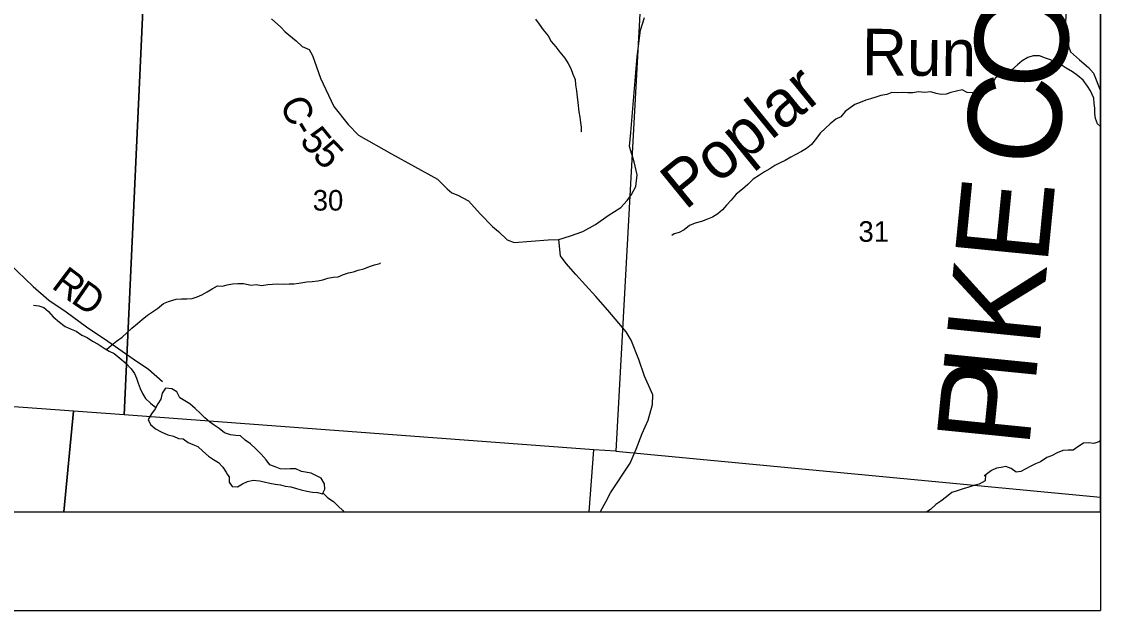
# Model space of a CAD drawing. Extents: x 5.6 to 39.6, y 0.7 to 22.7.
# Drawn here: x 12.858 to 15.052, y 14.707 to 15.903 of the extents above; entities that cross this region are included whole.
import ezdxf

# ---------------------------------------------------------------- set-up
doc = ezdxf.new("R2010")
doc.units = 0
doc.layers.add('Default', color=7, linetype='Continuous')
doc.layers.add('SH_Data', color=7, linetype='Continuous')

msp = doc.modelspace()

# ---------------------------------------------------------------- linework, layer by layer
at = {"layer": 'Default'}
for p, q in [((15.0518, 14.9373), (15.0518, 15.9625)), ((11.8881, 14.9074), (12.9445, 14.9074)), ((12.9445, 14.9074), (14.0121, 14.9074))]:
    msp.add_line(p, q, dxfattribs=at)
for points in [[(8.2518, 18.5322), (8.2518, 14.9074), (15.0518, 14.9074), (15.0518, 18.0251)], [(8.2518, 18.5322), (8.2518, 14.9074), (15.0518, 14.9074), (15.0518, 18.0251)], [(8.2518, 18.5322), (8.2518, 14.9074), (15.0518, 14.9074), (15.0518, 18.0251)], [(14.6817, 16.1552), (14.682, 16.155), (14.6933, 16.1477), (14.796, 16.0871), (14.8885, 16.041), (14.9244, 16.0245), (14.9584, 16.0122), (14.9777, 16.0079), (14.9931, 15.9968), (14.9999, 15.9804), (14.9894, 15.9452), (14.9817, 15.9221), (14.9808, 15.8936), (14.9863, 15.8556), (14.9911, 15.8416), (15.0092, 15.8255), (15.0277, 15.8099), (15.0378, 15.7984), (15.0518, 15.7628)], [(15.0518, 15.9625), (14.121, 16.0188), (14.0665, 15.031), (15.0518, 14.9373)], [(13.3666, 15.9088), (13.3855, 15.892), (13.3945, 15.8824), (13.4168, 15.8645), (13.4288, 15.8526), (13.4432, 15.8469), (13.4499, 15.8347), (13.4659, 15.7883), (13.4929, 15.7308), (13.5222, 15.6942), (13.5433, 15.6725), (13.6101, 15.6345), (13.7041, 15.5831), (13.7139, 15.5732), (13.7233, 15.5637), (13.7331, 15.5557), (13.7456, 15.5507), (13.7667, 15.5392), (13.7908, 15.5128), (13.816, 15.4869), (13.8277, 15.4766), (13.8454, 15.4598), (13.8598, 15.4548), (13.9291, 15.4597), (13.9504, 15.461), (13.9743, 15.468), (13.9993, 15.4771), (14.0251, 15.491), (14.051, 15.5091), (14.0765, 15.5257), (14.0898, 15.54), (14.0986, 15.5521), (14.1074, 15.5684), (14.1098, 15.5923), (14.1035, 15.6181), (14.0946, 15.6493), (14.0967, 15.6781), (14.1101, 15.8325), (14.1164, 15.8856), (14.1249, 15.9118)], [(13.9029, 15.9085), (13.9103, 15.8977), (13.9187, 15.8865), (13.9291, 15.8742), (13.9349, 15.863), (13.9448, 15.8518), (13.9529, 15.841), (13.9629, 15.8291), (13.9698, 15.8179), (13.9749, 15.8079), (13.9788, 15.7968), (13.9839, 15.7854), (13.9844, 15.7751), (13.9868, 15.7629), (13.988, 15.7504), (13.9893, 15.7386), (13.9911, 15.72), (13.9932, 15.7089), (13.9948, 15.6986), (13.9961, 15.6891), (13.9959, 15.6796), (13.9951, 15.6793)], [(15.0518, 15.6904), (15.0457, 15.6959), (15.0421, 15.7062), (15.0405, 15.7168), (15.0404, 15.7275), (15.039, 15.737), (15.0385, 15.748), (15.0313, 15.7626), (15.0254, 15.7722), (15.0166, 15.7845), (15.0055, 15.7939), (14.995, 15.8013), (14.982, 15.8088), (14.9719, 15.8151), (14.9614, 15.8199), (14.9501, 15.8258), (14.94, 15.8291), (14.9276, 15.8335), (14.9151, 15.8334), (14.9044, 15.8306), (14.8925, 15.8237), (14.8829, 15.8155), (14.872, 15.8052), (14.861, 15.8016), (14.8506, 15.7965), (14.8387, 15.7888), (14.8328, 15.7787), (14.8239, 15.7687), (14.812, 15.7625), (14.801, 15.7593), (14.7907, 15.7584), (14.7809, 15.759), (14.7704, 15.7646), (14.759, 15.7622), (14.7479, 15.7594), (14.7384, 15.7558), (14.7278, 15.7549), (14.718, 15.757), (14.7067, 15.7603), (14.6938, 15.7594), (14.6817, 15.7608), (14.6703, 15.7588), (14.6604, 15.7587), (14.6498, 15.7593), (14.6388, 15.7588), (14.6275, 15.759), (14.6172, 15.7554), (14.6054, 15.753), (14.5951, 15.7495), (14.584, 15.7467), (14.5745, 15.7439), (14.5634, 15.7392), (14.5527, 15.7352), (14.5431, 15.7283), (14.5327, 15.7209), (14.5238, 15.7101), (14.5138, 15.7054), (14.5022, 15.6954), (14.4926, 15.6869), (14.4817, 15.6765), (14.4747, 15.6664), (14.4642, 15.6538), (14.4541, 15.6453), (14.4438, 15.6394), (14.4323, 15.6332), (14.4223, 15.6278), (14.4108, 15.6208), (14.4005, 15.6161), (14.3901, 15.611), (14.3794, 15.6041), (14.3686, 15.5982), (14.3583, 15.5912), (14.346, 15.5832), (14.3351, 15.5724), (14.3243, 15.5628), (14.3112, 15.5525), (14.3007, 15.5406), (14.2914, 15.5305), (14.2836, 15.5208), (14.2736, 15.5131), (14.2628, 15.5061), (14.2529, 15.5022), (14.2406, 15.4975), (14.2281, 15.4936), (14.2162, 15.4889), (14.2054, 15.4805), (14.1954, 15.475), (14.1852, 15.4722), (14.1805, 15.4685)], [(12.3296, 15.7883), (12.339, 15.7727), (12.3492, 15.7574), (12.3601, 15.7441), (12.3774, 15.7307), (12.3955, 15.717), (12.4215, 15.688), (12.4611, 15.6623), (12.5233, 15.6229), (12.5788, 15.5895), (12.6272, 15.5653), (12.6498, 15.5527), (12.6846, 15.5396), (12.7061, 15.5239), (12.8338, 15.4112), (12.8817, 15.365), (12.9137, 15.3375), (12.9488, 15.3138), (12.9903, 15.2835), (13.0337, 15.2541), (13.085, 15.2181), (13.1166, 15.197), (13.1449, 15.1722)], [(14.0351, 14.9074), (14.0353, 14.9084), (14.046, 14.9277), (14.0555, 14.9463), (14.0955, 15.0065), (14.1081, 15.0349), (14.12, 15.0664), (14.1322, 15.0937), (14.1414, 15.1255), (14.1418, 15.1449), (14.1245, 15.1833), (14.1132, 15.2171), (14.0978, 15.2562), (14.0872, 15.273), (14.0501, 15.3175), (14.0259, 15.3446), (14.0048, 15.3682), (13.9855, 15.3895), (13.9654, 15.412), (13.9541, 15.4272), (13.9504, 15.461)], [(13.0309, 15.237), (13.0413, 15.2463), (13.0513, 15.254), (13.0628, 15.2621), (13.0725, 15.271), (13.0826, 15.2803), (13.0938, 15.2903), (13.1034, 15.2984), (13.1146, 15.3073), (13.1242, 15.3135), (13.1346, 15.3208), (13.1469, 15.3304), (13.1569, 15.3348), (13.1725, 15.3393), (13.1831, 15.3403), (13.1945, 15.3404), (13.2051, 15.3409), (13.2154, 15.3441), (13.225, 15.3484), (13.2357, 15.3546), (13.2457, 15.3605), (13.2564, 15.3663), (13.2667, 15.3661), (13.2766, 15.3689), (13.2872, 15.3706), (13.2978, 15.3711), (13.3092, 15.3712), (13.3254, 15.3678), (13.3349, 15.3691), (13.3462, 15.3674), (13.3588, 15.3694), (13.3686, 15.3703), (13.3796, 15.3704), (13.391, 15.3702), (13.402, 15.3707), (13.4118, 15.3709), (13.4221, 15.3721), (13.4384, 15.3744), (13.449, 15.3757), (13.4608, 15.377), (13.4711, 15.379), (13.481, 15.3822), (13.4916, 15.3839), (13.5019, 15.3852), (13.513, 15.3899), (13.5233, 15.3927), (13.5328, 15.3951), (13.5423, 15.3987), (13.5541, 15.4011), (13.566, 15.4061), (13.5755, 15.409), (13.5869, 15.4118), (13.5881, 15.4132)], [(12.8825, 15.3276), (12.8931, 15.3258), (12.9036, 15.3229), (12.9133, 15.3144), (12.9225, 15.3039), (12.9351, 15.293), (12.9471, 15.284), (12.9594, 15.2784), (12.9692, 15.2748), (12.9811, 15.2662), (12.9916, 15.2618), (13.0028, 15.254), (13.0137, 15.248), (13.0264, 15.2398), (13.0361, 15.2339), (13.0462, 15.2291), (13.0581, 15.2194), (13.0711, 15.2088), (13.0811, 15.198), (13.0881, 15.1884), (13.0916, 15.1788), (13.0956, 15.1689), (13.0995, 15.1581), (13.1038, 15.1478), (13.11, 15.1378), (13.1201, 15.1285), (13.1312, 15.1195)], [(12.9445, 14.9074), (12.9641, 15.1117), (12.0885, 15.1757), (11.9086, 15.1889), (11.8881, 14.9074)], [(13.4271, 14.9893), (13.4159, 14.9949), (13.4042, 14.9952), (13.3947, 14.9942), (13.3841, 14.9948), (13.3736, 14.9992), (13.3631, 15.0033), (13.3553, 15.0133), (13.3457, 15.0245), (13.3346, 15.0358), (13.3239, 15.0455), (13.313, 15.0529), (13.3034, 15.0622), (13.2936, 15.0624), (13.283, 15.0638), (13.271, 15.0679), (13.2598, 15.0765), (13.2501, 15.0839), (13.2404, 15.0906), (13.2307, 15.0984), (13.2211, 15.108), (13.2111, 15.1174), (13.2003, 15.1271), (13.1902, 15.133), (13.1801, 15.1393), (13.174, 15.1516), (13.1639, 15.1575), (13.151, 15.1585), (13.144, 15.1484), (13.1411, 15.1367), (13.1356, 15.127), (13.1296, 15.1169), (13.1222, 15.1064), (13.1159, 15.0952), (13.1202, 15.0849), (13.1303, 15.0763), (13.1419, 15.0704), (13.1557, 15.064), (13.167, 15.0611), (13.1771, 15.0563), (13.187, 15.0557), (13.1971, 15.0487), (13.2068, 15.0446), (13.2166, 15.0403), (13.2269, 15.0305), (13.2385, 15.0204), (13.2482, 15.0141), (13.2586, 15.0078), (13.2675, 14.9982), (13.2752, 14.987), (13.2759, 14.9851)], [(14.0121, 14.9074), (14.0218, 15.0338), (13.0667, 15.1046), (12.9641, 15.1117), (12.9445, 14.9074)], [(15.0518, 15.0518), (15.0487, 15.05), (15.0387, 15.0467), (15.0285, 15.048), (15.0175, 15.0468), (15.006, 15.0394), (14.9964, 15.0328), (14.9862, 15.0331), (14.9752, 15.0322), (14.9637, 15.0271), (14.9526, 15.0213), (14.943, 15.0177), (14.93, 15.0089), (14.92, 15.0049), (14.9105, 15.0006), (14.9001, 14.9951), (14.8901, 14.9897), (14.8803, 14.9884), (14.8706, 14.9958), (14.8597, 14.9998), (14.8502, 14.9974), (14.8403, 14.9961), (14.83, 14.9914), (14.8196, 14.9837), (14.8157, 14.9803)], [(13.2759, 14.9851), (13.2804, 14.9788), (13.2805, 14.9681), (13.2862, 14.9587), (13.2975, 14.9583), (13.3077, 14.9644), (13.3179, 14.9693), (13.3289, 14.972), (13.3418, 14.9705), (13.3516, 14.9686), (13.363, 14.966), (13.374, 14.9637), (13.385, 14.9626), (13.3944, 14.96), (13.4058, 14.9581), (13.4175, 14.9547), (13.427, 14.9521), (13.4384, 14.9494), (13.4497, 14.9476), (13.46, 14.9468), (13.4698, 14.9442), (13.4747, 14.9537), (13.4743, 14.9643), (13.4671, 14.9761), (13.4565, 14.9813), (13.447, 14.9859), (13.4271, 14.9893)], [(14.818, 14.9824), (14.8173, 14.9705), (14.8052, 14.964), (14.7942, 14.961), (14.784, 14.9575), (14.7726, 14.9545), (14.7605, 14.9503), (14.7499, 14.9468), (14.739, 14.9381), (14.7272, 14.9293), (14.717, 14.9225), (14.7061, 14.9126), (14.6991, 14.9074)], [(13.4708, 14.9461), (13.4808, 14.9362), (13.4922, 14.9287), (13.5021, 14.9192), (13.5115, 14.9105), (13.5138, 14.9074)]]:
    msp.add_lwpolyline(points, dxfattribs=at)
for points in [[(12.1494, 16.1525), (13.1121, 16.0885), (13.0667, 15.1046), (12.9641, 15.1117), (12.0885, 15.1757)], [(13.1121, 16.0885), (14.121, 16.0188), (14.0665, 15.031), (14.0218, 15.0338), (13.0667, 15.1046)]]:
    msp.add_lwpolyline(points, close=True, dxfattribs=at)
at = {"layer": 'SH_Data'}
for p in [(15.0518, 21.7074), (8.0518, 14.7074)]:
    msp.add_line(p, (15.0518, 14.7074), dxfattribs=at)

# ---------------------------------------------------------------- texts
at = {"layer": 'Default'}
for s, height, rotation, p in [('O', 0.1894, 84.9739, (14.9774, 15.7605)), ('Run', 0.09469, 359.524, (14.5665, 15.7942)), ('Poplar', 0.0947, 39.1794, (14.2077, 15.5189)), ('C', 0.1894, 84.7044, (14.9631, 15.6058)), ('C', 0.0568, 294.3199, (13.3823, 15.7368)), ('-', 0.0568, 301.1851, (13.405, 15.6877)), ('5', 0.0568, 309.1047, (13.422, 15.6608)), ('5', 0.0568, 313.912, (13.4476, 15.6297)), ('E', 0.1894, 84.3689, (14.9436, 15.4063)), ('30', 0.04182, 0, (13.4502, 15.5194)), ('31', 0.04182, 0, (14.5598, 15.456)), ('R', 0.0568, 322.8959, (12.917, 15.3638)), ('K', 0.1894, 84.2812, (14.9269, 15.2397)), ('D', 0.0568, 325.4397, (12.9564, 15.3341)), ('I', 0.1894, 84.2772, (14.9192, 15.1629)), ('P', 0.1894, 84.279, (14.9064, 15.0348))]:
    msp.add_text(s, height=height, rotation=rotation, dxfattribs=at).set_placement(p)

doc.saveas('drawing.dxf')
